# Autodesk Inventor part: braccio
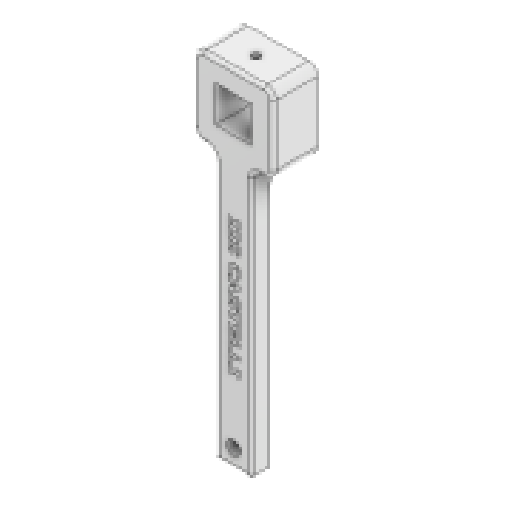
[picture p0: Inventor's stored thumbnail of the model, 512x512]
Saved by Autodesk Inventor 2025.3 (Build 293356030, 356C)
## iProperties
Created: 2025-09
Part Number: braccio
Material: Plastica ABS
Document SubType Name: Modeling
Designer: Ryzen5700u
Density: 1.06 g/cm^3
Appearance: Liscia - Bianco
Author: Ryzen5700u
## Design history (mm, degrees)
sketch "Schizzo1"
  geometry: L1 (-10.05, -10.05)-(10.05, -10.05); L2 (10.05, -10.05)-(10.05, 10.05); L3 (10.05, 10.05)-(-10.05, 10.05); L4 (-10.05, 10.05)-(-10.05, -10.05); L5 (-10.05, -10.05)-(10.05, 10.05); L6 (10.05, -10.05)-(-10.05, 10.05); L7 (-22, -22)-(22, -22); L8 (22, -22)-(22, 22); L9 (22, 22)-(-22, 22); L10 (-22, 22)-(-22, -22); L11 (-22, -22)-(22, 22); L12 (22, -22)-(-22, 22); L13 (-10, -22)-(10, -22); L14 (10, -22)-(10, -172); L15 (10, -172)-(-10, -172); L16 (-10, -172)-(-10, -22); 2 further points
  constraints: 32 end point, 6 parallel, 4 midpoint, 3 horizontal, 3 perpendicular, 1 point on line
  dimensions: "d0" = 20.1 distance of L3.end L2.end; "d1" = 20.1 distance of L2.end L1.end; "d2" = 44 distance of L9.end L8.end; "d3" = 44 distance of L7.end L8.end; "d4" = 150 distance of L13.end L14.end
extrude "Estrusione1" new body sketch "Schizzo1" distance "d5" = 10; taper "d6" = 0 deg
sketch "Schizzo2"
  geometry: L1 (22, -22)-(10, -22) reference; L2 (22, 22)-(22, -22) reference; L3 (-22, 22)-(22, 22) reference; L4 (-22, -22)-(-22, 22) reference; L5 (-10, -22)-(-22, -22) reference; L6 (-10, -172)-(-10, -22) reference; L7 (10, -172)-(-10, -172) reference; L8 (10, -22)-(10, -172) reference; L9 (10.05, -10.05)-(10.05, 10.05) reference; L10 (-10.05, -10.05)-(10.05, -10.05) reference; L11 (-10.05, 10.05)-(-10.05, -10.05) reference; L12 (10.05, 10.05)-(-10.05, 10.05) reference; L13 (10, -22)-(-10, -22); 1 further point
  constraints: 2 end point, 1 horizontal
extrude "Estrusione2" join sketch "Schizzo2" distance "d7" = 15; taper "d8" = 0 deg
sketch "Schizzo3"
  geometry: L1 (44, 25)-(44, 0) reference; L2 (44, 25)-(0, 25) reference; L3 (44, 0)-(0, 25); L4 (0, 0)-(0, 25) reference; L5 (0, 25)-(0, 0); L6 (0, 0)-(44, 25); 2 further points
  constraints: 6 end point, 2 midpoint, 1 collinear
hole "Foro1" sketch "Schizzo3" at (22, 12.5) diameter "d9" = 4.5; stored, may be unused: countersink angle "d13" = 90 deg, drill point angle "d15" = 118 deg; dims "d10" = 6, "d11" = 10, "d12" = 5.7, "d14" = 64.25
fillet "Raccordo1" dims "d16" = 5
sketch "Schizzo4"
  geometry: L1 (4.5, -162)-(2.25, -165.897); L2 (2.25, -165.897)-(-2.25, -165.897); L3 (-2.25, -165.897)-(-4.5, -162); L4 (-4.5, -162)-(-2.25, -158.103); L5 (-2.25, -158.103)-(2.25, -158.103); L6 (2.25, -158.103)-(4.5, -162); C1 r 4 at (0, -162) reference; 2 further points
  constraints: 12 end point, 1 coincident, 13 other
  dimensions: "d21" = 4.5 distance of L4.end L5.end
extrude "Estrusione3" cut sketch "Schizzo4" distance "d17" = 4; taper "d18" = 0 deg
sketch "Schizzo5"
  geometry: C1 r 2.25 at (0, -162) reference; 1 further point
extrude "Estrusione4" cut sketch "Schizzo5" extent not by distance; stored distance "d19" = 4; taper "d20" = 0 deg
sketch "Schizzo6"
  geometry: L1 (3.332, -49.867)-(3.332, -144.876); L2 (3.332, -144.876)-(-4.284, -144.876); L3 (-4.284, -144.876)-(-4.284, -49.867); L4 (-4.284, -49.867)-(3.332, -49.867); 1 further point
  constraints: 2 other
extrude "Estrusione5" cut sketch "Schizzo6" distance "d23" = 0.2; taper "d24" = 0 deg
fillet "Raccordo3" dims "d25" = 15
fillet "Raccordo4" dims "d26" = 1
fillet "Raccordo5" dims "d27" = 2
node "Solido1"
node "Linea chiusa proiettata1"
node "Riferimento1"
node "Riferimento2"
